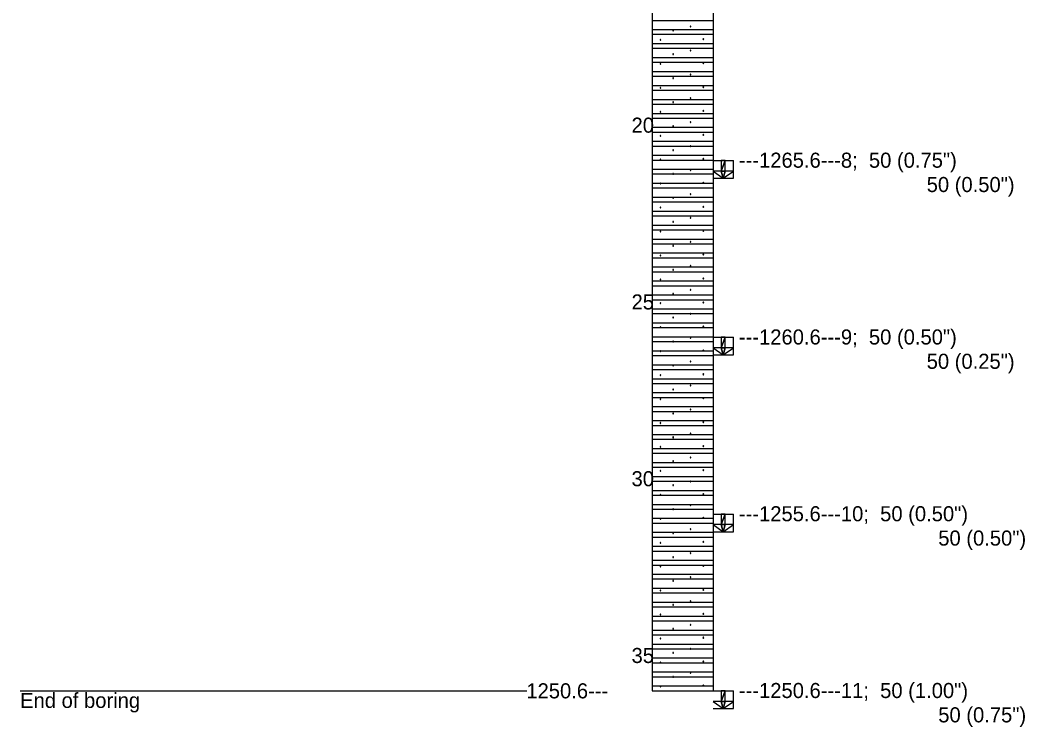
# Model space of a CAD drawing. Extents: x -6 to 173, y 24 to 64.
# Drawn here: x 152.93 to 161.19, y 38.73 to 44.54 of the extents above; entities that cross this region are included whole.
import ezdxf

# ---------------------------------------------------------------- set-up
doc = ezdxf.new("R2010")
doc.units = 0

msp = doc.modelspace()

# ---------------------------------------------------------------- linework, layer by layer
for points in [[(158.1273, 49.4948), (158.1273, 39.0297)], [(158.6273, 49.4948), (158.6273, 39.0297)], [(158.1273, 44.5426), (158.6273, 44.5426)], [(158.1273, 44.4671), (158.6273, 44.4671)], [(158.3024, 44.4605), (158.3008, 44.4634), (158.2975, 44.4634), (158.2958, 44.4606), (158.2975, 44.4577), (158.3008, 44.4577), (158.3024, 44.4605)], [(158.445, 44.4924), (158.4434, 44.4952), (158.4401, 44.4952), (158.4384, 44.4924), (158.4401, 44.4896), (158.4434, 44.4896), (158.445, 44.4924)], [(158.1273, 44.4277), (158.6273, 44.4277)], [(158.1977, 44.3816), (158.1961, 44.3844), (158.1928, 44.3844), (158.1912, 44.3816), (158.1928, 44.3787), (158.1961, 44.3787), (158.1977, 44.3816)], [(158.5505, 44.388), (158.5489, 44.3909), (158.5456, 44.3909), (158.5439, 44.388), (158.5456, 44.3852), (158.5489, 44.3852), (158.5505, 44.388)], [(158.1273, 44.3523), (158.6273, 44.3523)], [(158.1273, 44.3129), (158.6273, 44.3129)], [(158.445, 44.2955), (158.4434, 44.2984), (158.4401, 44.2984), (158.4384, 44.2955), (158.4401, 44.2927), (158.4434, 44.2927), (158.445, 44.2955)], [(158.1273, 44.2375), (158.6273, 44.2375)], [(158.1273, 44.1981), (158.6273, 44.1981)], [(158.3024, 44.2636), (158.3008, 44.2665), (158.2975, 44.2665), (158.2958, 44.2637), (158.2975, 44.2608), (158.3008, 44.2608), (158.3024, 44.2636)], [(158.5505, 44.1912), (158.5489, 44.1941), (158.5456, 44.1941), (158.5439, 44.1912), (158.5456, 44.1884), (158.5489, 44.1884), (158.5505, 44.1912)], [(158.1273, 44.1226), (158.6273, 44.1226)], [(158.1977, 44.1847), (158.1961, 44.1875), (158.1928, 44.1875), (158.1912, 44.1847), (158.1928, 44.1818), (158.1961, 44.1818), (158.1977, 44.1847)], [(158.1273, 44.0833), (158.6273, 44.0833)], [(158.3024, 44.0668), (158.3008, 44.0697), (158.2975, 44.0697), (158.2958, 44.0669), (158.2975, 44.064), (158.3008, 44.064), (158.3024, 44.0668)], [(158.445, 44.0987), (158.4434, 44.1015), (158.4401, 44.1015), (158.4384, 44.0987), (158.4401, 44.0959), (158.4434, 44.0959), (158.445, 44.0987)], [(158.1273, 44.0078), (158.6273, 44.0078)], [(158.1273, 43.9684), (158.6273, 43.9684)], [(158.1977, 43.9879), (158.1961, 43.9907), (158.1928, 43.9907), (158.1912, 43.9879), (158.1928, 43.985), (158.1961, 43.985), (158.1977, 43.9879)], [(158.5505, 43.9943), (158.5489, 43.9972), (158.5456, 43.9972), (158.5439, 43.9943), (158.5456, 43.9915), (158.5489, 43.9915), (158.5505, 43.9943)], [(158.1273, 43.893), (158.6273, 43.893)], [(158.3024, 43.8699), (158.3008, 43.8728), (158.2975, 43.8728), (158.2958, 43.87), (158.2975, 43.8671), (158.3008, 43.8671), (158.3024, 43.8699)], [(158.445, 43.9018), (158.4434, 43.9047), (158.4401, 43.9047), (158.4384, 43.9018), (158.4401, 43.899), (158.4434, 43.899), (158.445, 43.9018)], [(158.1273, 43.8536), (158.6273, 43.8536)], [(158.1977, 43.791), (158.1961, 43.7938), (158.1928, 43.7938), (158.1912, 43.791), (158.1928, 43.7881), (158.1961, 43.7881), (158.1977, 43.791)], [(158.5505, 43.7975), (158.5489, 43.8004), (158.5456, 43.8004), (158.5439, 43.7975), (158.5456, 43.7947), (158.5489, 43.7947), (158.5505, 43.7975)], [(158.1273, 43.7781), (158.6273, 43.7781)], [(158.1273, 43.7388), (158.6273, 43.7388)], [(158.445, 43.705), (158.4434, 43.7078), (158.4401, 43.7078), (158.4384, 43.705), (158.4401, 43.7022), (158.4434, 43.7022), (158.445, 43.705)], [(158.1273, 43.6633), (158.6273, 43.6633)], [(158.1273, 43.6239), (158.6273, 43.6239)], [(158.3024, 43.6731), (158.3008, 43.676), (158.2975, 43.676), (158.2958, 43.6732), (158.2975, 43.6703), (158.3008, 43.6703), (158.3024, 43.6731)], [(158.1273, 43.5485), (158.6273, 43.5485)], [(158.1977, 43.5942), (158.1961, 43.597), (158.1928, 43.597), (158.1912, 43.5942), (158.1928, 43.5913), (158.1961, 43.5913), (158.1977, 43.5942)], [(158.5505, 43.6006), (158.5489, 43.6035), (158.5456, 43.6035), (158.5439, 43.6006), (158.5456, 43.5978), (158.5489, 43.5978), (158.5505, 43.6006)], [(158.1273, 43.5091), (158.6273, 43.5091)], [(158.3024, 43.4762), (158.3008, 43.4791), (158.2975, 43.4791), (158.2958, 43.4763), (158.2975, 43.4734), (158.3008, 43.4734), (158.3024, 43.4762)], [(158.445, 43.5081), (158.4434, 43.5109), (158.4401, 43.5109), (158.4384, 43.5081), (158.4401, 43.5053), (158.4434, 43.5053), (158.445, 43.5081)], [(158.1273, 43.4337), (158.6273, 43.4337)], [(158.1273, 43.3943), (158.6273, 43.3943)], [(158.1977, 43.3973), (158.1961, 43.4001), (158.1928, 43.4001), (158.1912, 43.3973), (158.1928, 43.3944), (158.1961, 43.3944), (158.1977, 43.3973)], [(158.5505, 43.4038), (158.5489, 43.4067), (158.5456, 43.4067), (158.5439, 43.4038), (158.5456, 43.401), (158.5489, 43.401), (158.5505, 43.4038)], [(158.6273, 43.3902), (158.794, 43.3902)], [(158.794, 43.2448), (158.794, 43.3902)], [(158.1273, 43.3188), (158.6273, 43.3188)], [(158.445, 43.3113), (158.4434, 43.3141), (158.4401, 43.3141), (158.4384, 43.3113), (158.4401, 43.3085), (158.4434, 43.3085), (158.445, 43.3113)], [(158.1273, 43.2795), (158.6273, 43.2795)], [(158.1273, 43.204), (158.6273, 43.204)], [(158.1977, 43.2005), (158.1961, 43.2033), (158.1928, 43.2033), (158.1912, 43.2005), (158.1928, 43.1976), (158.1961, 43.1976), (158.1977, 43.2005)], [(158.3024, 43.2794), (158.3008, 43.2823), (158.2975, 43.2823), (158.2958, 43.2795), (158.2975, 43.2766), (158.3008, 43.2766), (158.3024, 43.2794)], [(158.5505, 43.2069), (158.5489, 43.2098), (158.5456, 43.2098), (158.5439, 43.2069), (158.5456, 43.2041), (158.5489, 43.2041), (158.5505, 43.2069)], [(158.6273, 43.2448), (158.794, 43.2448)], [(158.1273, 43.1646), (158.6273, 43.1646)], [(158.1273, 43.0892), (158.6273, 43.0892)], [(158.1273, 43.0498), (158.6273, 43.0498)], [(158.3024, 43.0825), (158.3008, 43.0854), (158.2975, 43.0854), (158.2958, 43.0826), (158.2975, 43.0797), (158.3008, 43.0797), (158.3024, 43.0825)], [(158.445, 43.1144), (158.4434, 43.1172), (158.4401, 43.1172), (158.4384, 43.1144), (158.4401, 43.1116), (158.4434, 43.1116), (158.445, 43.1144)], [(158.1273, 42.9743), (158.6273, 42.9743)], [(158.1977, 43.0036), (158.1961, 43.0064), (158.1928, 43.0064), (158.1912, 43.0036), (158.1928, 43.0007), (158.1961, 43.0007), (158.1977, 43.0036)], [(158.5505, 43.0101), (158.5489, 43.013), (158.5456, 43.013), (158.5439, 43.0101), (158.5456, 43.0073), (158.5489, 43.0073), (158.5505, 43.0101)], [(158.1273, 42.935), (158.6273, 42.935)], [(158.3024, 42.8857), (158.3008, 42.8886), (158.2975, 42.8886), (158.2958, 42.8858), (158.2975, 42.8829), (158.3008, 42.8829), (158.3024, 42.8857)], [(158.445, 42.9176), (158.4434, 42.9204), (158.4401, 42.9204), (158.4384, 42.9176), (158.4401, 42.9148), (158.4434, 42.9148), (158.445, 42.9176)], [(158.1273, 42.8595), (158.6273, 42.8595)], [(158.1273, 42.8201), (158.6273, 42.8201)], [(158.1977, 42.8068), (158.1961, 42.8096), (158.1928, 42.8096), (158.1912, 42.8068), (158.1928, 42.8039), (158.1961, 42.8039), (158.1977, 42.8068)], [(158.5505, 42.8132), (158.5489, 42.8161), (158.5456, 42.8161), (158.5439, 42.8132), (158.5456, 42.8104), (158.5489, 42.8104), (158.5505, 42.8132)], [(158.1273, 42.7447), (158.6273, 42.7447)], [(158.1273, 42.7053), (158.6273, 42.7053)], [(158.445, 42.7207), (158.4434, 42.7235), (158.4401, 42.7235), (158.4384, 42.7207), (158.4401, 42.7179), (158.4434, 42.7179), (158.445, 42.7207)], [(158.1273, 42.6298), (158.6273, 42.6298)], [(158.3024, 42.6888), (158.3008, 42.6917), (158.2975, 42.6917), (158.2958, 42.6889), (158.2975, 42.686), (158.3008, 42.686), (158.3024, 42.6888)], [(158.1273, 42.5905), (158.6273, 42.5905)], [(158.1977, 42.6099), (158.1961, 42.6127), (158.1928, 42.6127), (158.1912, 42.6099), (158.1928, 42.607), (158.1961, 42.607), (158.1977, 42.6099)], [(158.5505, 42.6164), (158.5489, 42.6193), (158.5456, 42.6193), (158.5439, 42.6164), (158.5456, 42.6136), (158.5489, 42.6136), (158.5505, 42.6164)], [(158.1273, 42.515), (158.6273, 42.515)], [(158.1273, 42.4756), (158.6273, 42.4756)], [(158.3024, 42.492), (158.3008, 42.4949), (158.2975, 42.4949), (158.2958, 42.4921), (158.2975, 42.4892), (158.3008, 42.4892), (158.3024, 42.492)], [(158.445, 42.5239), (158.4434, 42.5267), (158.4401, 42.5267), (158.4384, 42.5239), (158.4401, 42.5211), (158.4434, 42.5211), (158.445, 42.5239)], [(158.1273, 42.4002), (158.6273, 42.4002)], [(158.1977, 42.413), (158.1961, 42.4159), (158.1928, 42.4159), (158.1912, 42.413), (158.1928, 42.4102), (158.1961, 42.4102), (158.1977, 42.413)], [(158.5505, 42.4195), (158.5489, 42.4224), (158.5456, 42.4224), (158.5439, 42.4195), (158.5456, 42.4167), (158.5489, 42.4167), (158.5505, 42.4195)], [(158.1273, 42.3608), (158.6273, 42.3608)], [(158.3024, 42.2951), (158.3008, 42.298), (158.2975, 42.298), (158.2958, 42.2952), (158.2975, 42.2923), (158.3008, 42.2923), (158.3024, 42.2951)], [(158.445, 42.327), (158.4434, 42.3298), (158.4401, 42.3298), (158.4384, 42.327), (158.4401, 42.3242), (158.4434, 42.3242), (158.445, 42.327)], [(158.1273, 42.2854), (158.6273, 42.2854)], [(158.1273, 42.246), (158.6273, 42.246)], [(158.1977, 42.2162), (158.1961, 42.219), (158.1928, 42.219), (158.1912, 42.2162), (158.1928, 42.2133), (158.1961, 42.2133), (158.1977, 42.2162)], [(158.5505, 42.2227), (158.5489, 42.2256), (158.5456, 42.2256), (158.5439, 42.2227), (158.5456, 42.2199), (158.5489, 42.2199), (158.5505, 42.2227)], [(158.1273, 42.1705), (158.6273, 42.1705)], [(158.1273, 42.1312), (158.6273, 42.1312)], [(158.445, 42.1302), (158.4434, 42.133), (158.4401, 42.133), (158.4384, 42.1302), (158.4401, 42.1274), (158.4434, 42.1274), (158.445, 42.1302)], [(158.1273, 42.0557), (158.6273, 42.0557)], [(158.3024, 42.0983), (158.3008, 42.1012), (158.2975, 42.1012), (158.2958, 42.0984), (158.2975, 42.0955), (158.3008, 42.0955), (158.3024, 42.0983)], [(158.1273, 42.0163), (158.6273, 42.0163)], [(158.1977, 42.0193), (158.1961, 42.0222), (158.1928, 42.0222), (158.1912, 42.0193), (158.1928, 42.0165), (158.1961, 42.0165), (158.1977, 42.0193)], [(158.5505, 42.0258), (158.5489, 42.0287), (158.5456, 42.0287), (158.5439, 42.0258), (158.5456, 42.023), (158.5489, 42.023), (158.5505, 42.0258)], [(158.1273, 41.9409), (158.6273, 41.9409)], [(158.1273, 41.9015), (158.6273, 41.9015)], [(158.3024, 41.9014), (158.3008, 41.9043), (158.2975, 41.9043), (158.2958, 41.9015), (158.2975, 41.8986), (158.3008, 41.8986), (158.3024, 41.9014)], [(158.445, 41.9333), (158.4434, 41.9361), (158.4401, 41.9361), (158.4384, 41.9333), (158.4401, 41.9305), (158.4434, 41.9305), (158.445, 41.9333)], [(158.6273, 41.9367), (158.794, 41.9367)], [(158.794, 41.7913), (158.794, 41.9367)], [(158.1273, 41.826), (158.6273, 41.826)], [(158.1977, 41.8225), (158.1961, 41.8253), (158.1928, 41.8253), (158.1912, 41.8225), (158.1928, 41.8196), (158.1961, 41.8196), (158.1977, 41.8225)], [(158.5505, 41.829), (158.5489, 41.8319), (158.5456, 41.8319), (158.5439, 41.829), (158.5456, 41.8262), (158.5489, 41.8262), (158.5505, 41.829)], [(158.1273, 41.7867), (158.6273, 41.7867)], [(158.445, 41.7365), (158.4434, 41.7393), (158.4401, 41.7393), (158.4384, 41.7365), (158.4401, 41.7337), (158.4434, 41.7337), (158.445, 41.7365)], [(158.6273, 41.7913), (158.794, 41.7913)], [(158.1273, 41.7112), (158.6273, 41.7112)], [(158.1273, 41.6718), (158.6273, 41.6718)], [(158.3024, 41.7046), (158.3008, 41.7075), (158.2975, 41.7075), (158.2958, 41.7047), (158.2975, 41.7018), (158.3008, 41.7018), (158.3024, 41.7046)], [(158.5505, 41.6321), (158.5489, 41.635), (158.5456, 41.635), (158.5439, 41.6321), (158.5456, 41.6293), (158.5489, 41.6293), (158.5505, 41.6321)], [(158.1273, 41.5964), (158.6273, 41.5964)], [(158.1273, 41.557), (158.6273, 41.557)], [(158.1977, 41.6256), (158.1961, 41.6285), (158.1928, 41.6285), (158.1912, 41.6256), (158.1928, 41.6228), (158.1961, 41.6228), (158.1977, 41.6256)], [(158.1273, 41.4816), (158.6273, 41.4816)], [(158.3024, 41.5077), (158.3008, 41.5106), (158.2975, 41.5106), (158.2958, 41.5078), (158.2975, 41.5049), (158.3008, 41.5049), (158.3024, 41.5077)], [(158.445, 41.5396), (158.4434, 41.5424), (158.4401, 41.5424), (158.4384, 41.5396), (158.4401, 41.5368), (158.4434, 41.5368), (158.445, 41.5396)], [(158.1273, 41.4422), (158.6273, 41.4422)], [(158.1977, 41.4288), (158.1961, 41.4316), (158.1928, 41.4316), (158.1912, 41.4288), (158.1928, 41.4259), (158.1961, 41.4259), (158.1977, 41.4288)], [(158.5505, 41.4353), (158.5489, 41.4382), (158.5456, 41.4382), (158.5439, 41.4353), (158.5456, 41.4325), (158.5489, 41.4325), (158.5505, 41.4353)], [(158.1273, 41.3667), (158.6273, 41.3667)], [(158.1273, 41.3274), (158.6273, 41.3274)], [(158.3024, 41.3109), (158.3008, 41.3138), (158.2975, 41.3138), (158.2958, 41.3109), (158.2975, 41.3081), (158.3008, 41.3081), (158.3024, 41.3109)], [(158.445, 41.3428), (158.4434, 41.3456), (158.4401, 41.3456), (158.4384, 41.3428), (158.4401, 41.34), (158.4434, 41.34), (158.445, 41.3428)], [(158.1273, 41.2519), (158.6273, 41.2519)], [(158.1977, 41.2319), (158.1961, 41.2348), (158.1928, 41.2348), (158.1912, 41.2319), (158.1928, 41.2291), (158.1961, 41.2291), (158.1977, 41.2319)], [(158.5505, 41.2384), (158.5489, 41.2413), (158.5456, 41.2413), (158.5439, 41.2384), (158.5456, 41.2356), (158.5489, 41.2356), (158.5505, 41.2384)], [(158.1273, 41.2125), (158.6273, 41.2125)], [(158.1273, 41.1371), (158.6273, 41.1371)], [(158.445, 41.1459), (158.4434, 41.1487), (158.4401, 41.1487), (158.4384, 41.1459), (158.4401, 41.1431), (158.4434, 41.1431), (158.445, 41.1459)], [(158.1273, 41.0977), (158.6273, 41.0977)], [(158.3024, 41.114), (158.3008, 41.1169), (158.2975, 41.1169), (158.2958, 41.1141), (158.2975, 41.1112), (158.3008, 41.1112), (158.3024, 41.114)], [(158.1273, 41.0222), (158.6273, 41.0222)], [(158.1273, 40.9829), (158.6273, 40.9829)], [(158.1977, 41.0351), (158.1961, 41.0379), (158.1928, 41.0379), (158.1912, 41.0351), (158.1928, 41.0322), (158.1961, 41.0322), (158.1977, 41.0351)], [(158.5505, 41.0416), (158.5489, 41.0445), (158.5456, 41.0445), (158.5439, 41.0416), (158.5456, 41.0388), (158.5489, 41.0388), (158.5505, 41.0416)], [(158.1273, 40.9074), (158.6273, 40.9074)], [(158.3024, 40.9172), (158.3008, 40.9201), (158.2975, 40.9201), (158.2958, 40.9172), (158.2975, 40.9144), (158.3008, 40.9144), (158.3024, 40.9172)], [(158.445, 40.9491), (158.4434, 40.9519), (158.4401, 40.9519), (158.4384, 40.9491), (158.4401, 40.9463), (158.4434, 40.9463), (158.445, 40.9491)], [(158.1273, 40.868), (158.6273, 40.868)], [(158.1977, 40.8382), (158.1961, 40.8411), (158.1928, 40.8411), (158.1912, 40.8382), (158.1928, 40.8354), (158.1961, 40.8354), (158.1977, 40.8382)], [(158.5505, 40.8447), (158.5489, 40.8476), (158.5456, 40.8476), (158.5439, 40.8447), (158.5456, 40.8419), (158.5489, 40.8419), (158.5505, 40.8447)], [(158.1273, 40.7926), (158.6273, 40.7926)], [(158.1273, 40.7532), (158.6273, 40.7532)], [(158.3024, 40.7203), (158.3008, 40.7232), (158.2975, 40.7232), (158.2958, 40.7204), (158.2975, 40.7175), (158.3008, 40.7175), (158.3024, 40.7203)], [(158.445, 40.7522), (158.4434, 40.755), (158.4401, 40.755), (158.4384, 40.7522), (158.4401, 40.7494), (158.4434, 40.7494), (158.445, 40.7522)], [(158.1273, 40.6777), (158.6273, 40.6777)], [(158.1977, 40.6414), (158.1961, 40.6442), (158.1928, 40.6442), (158.1912, 40.6414), (158.1928, 40.6385), (158.1961, 40.6385), (158.1977, 40.6414)], [(158.5505, 40.6479), (158.5489, 40.6508), (158.5456, 40.6508), (158.5439, 40.6479), (158.5456, 40.6451), (158.5489, 40.6451), (158.5505, 40.6479)], [(158.1273, 40.6384), (158.6273, 40.6384)], [(158.1273, 40.5629), (158.6273, 40.5629)], [(158.445, 40.5554), (158.4434, 40.5582), (158.4401, 40.5582), (158.4384, 40.5554), (158.4401, 40.5526), (158.4434, 40.5526), (158.445, 40.5554)], [(158.1273, 40.5235), (158.6273, 40.5235)], [(158.3024, 40.5235), (158.3008, 40.5264), (158.2975, 40.5264), (158.2958, 40.5235), (158.2975, 40.5207), (158.3008, 40.5207), (158.3024, 40.5235)], [(158.6273, 40.4832), (158.794, 40.4832)], [(158.794, 40.3378), (158.794, 40.4832)], [(158.1273, 40.4481), (158.6273, 40.4481)], [(158.1273, 40.4087), (158.6273, 40.4087)], [(158.1977, 40.4445), (158.1961, 40.4474), (158.1928, 40.4474), (158.1912, 40.4445), (158.1928, 40.4417), (158.1961, 40.4417), (158.1977, 40.4445)], [(158.5505, 40.451), (158.5489, 40.4539), (158.5456, 40.4539), (158.5439, 40.451), (158.5456, 40.4482), (158.5489, 40.4482), (158.5505, 40.451)], [(158.1273, 40.3333), (158.6273, 40.3333)], [(158.3024, 40.3266), (158.3008, 40.3295), (158.2975, 40.3295), (158.2958, 40.3267), (158.2975, 40.3238), (158.3008, 40.3238), (158.3024, 40.3266)], [(158.445, 40.3585), (158.4434, 40.3613), (158.4401, 40.3613), (158.4384, 40.3585), (158.4401, 40.3557), (158.4434, 40.3557), (158.445, 40.3585)], [(158.6273, 40.3378), (158.794, 40.3378)], [(158.1273, 40.2939), (158.6273, 40.2939)], [(158.1977, 40.2477), (158.1961, 40.2505), (158.1928, 40.2505), (158.1912, 40.2477), (158.1928, 40.2448), (158.1961, 40.2448), (158.1977, 40.2477)], [(158.5505, 40.2542), (158.5489, 40.2571), (158.5456, 40.2571), (158.5439, 40.2542), (158.5456, 40.2514), (158.5489, 40.2514), (158.5505, 40.2542)], [(158.1273, 40.2184), (158.6273, 40.2184)], [(158.1273, 40.1791), (158.6273, 40.1791)], [(158.445, 40.1617), (158.4434, 40.1645), (158.4401, 40.1645), (158.4384, 40.1617), (158.4401, 40.1588), (158.4434, 40.1588), (158.445, 40.1617)], [(158.1273, 40.1036), (158.6273, 40.1036)], [(158.1273, 40.0642), (158.6273, 40.0642)], [(158.3024, 40.1298), (158.3008, 40.1327), (158.2975, 40.1327), (158.2958, 40.1298), (158.2975, 40.127), (158.3008, 40.127), (158.3024, 40.1298)], [(158.1273, 39.9888), (158.6273, 39.9888)], [(158.1977, 40.0508), (158.1961, 40.0537), (158.1928, 40.0537), (158.1912, 40.0508), (158.1928, 40.048), (158.1961, 40.048), (158.1977, 40.0508)], [(158.5505, 40.0573), (158.5489, 40.0602), (158.5456, 40.0602), (158.5439, 40.0573), (158.5456, 40.0545), (158.5489, 40.0545), (158.5505, 40.0573)], [(158.1273, 39.9494), (158.6273, 39.9494)], [(158.3024, 39.9329), (158.3008, 39.9358), (158.2975, 39.9358), (158.2958, 39.933), (158.2975, 39.9301), (158.3008, 39.9301), (158.3024, 39.9329)], [(158.445, 39.9648), (158.4434, 39.9676), (158.4401, 39.9676), (158.4384, 39.9648), (158.4401, 39.962), (158.4434, 39.962), (158.445, 39.9648)], [(158.1273, 39.8739), (158.6273, 39.8739)], [(158.1273, 39.8346), (158.6273, 39.8346)], [(158.1977, 39.854), (158.1961, 39.8568), (158.1928, 39.8568), (158.1912, 39.854), (158.1928, 39.8511), (158.1961, 39.8511), (158.1977, 39.854)], [(158.5505, 39.8605), (158.5489, 39.8634), (158.5456, 39.8634), (158.5439, 39.8605), (158.5456, 39.8577), (158.5489, 39.8577), (158.5505, 39.8605)], [(158.1273, 39.7591), (158.6273, 39.7591)], [(158.3024, 39.7361), (158.3008, 39.739), (158.2975, 39.739), (158.2958, 39.7361), (158.2975, 39.7333), (158.3008, 39.7333), (158.3024, 39.7361)], [(158.445, 39.768), (158.4434, 39.7708), (158.4401, 39.7708), (158.4384, 39.768), (158.4401, 39.7651), (158.4434, 39.7651), (158.445, 39.768)], [(158.1273, 39.7197), (158.6273, 39.7197)], [(158.1977, 39.6571), (158.1961, 39.66), (158.1928, 39.66), (158.1912, 39.6571), (158.1928, 39.6543), (158.1961, 39.6543), (158.1977, 39.6571)], [(158.5505, 39.6636), (158.5489, 39.6665), (158.5456, 39.6665), (158.5439, 39.6636), (158.5456, 39.6608), (158.5489, 39.6608), (158.5505, 39.6636)], [(158.1273, 39.6443), (158.6273, 39.6443)], [(158.1273, 39.6049), (158.6273, 39.6049)], [(158.445, 39.5711), (158.4434, 39.5739), (158.4401, 39.5739), (158.4384, 39.5711), (158.4401, 39.5683), (158.4434, 39.5683), (158.445, 39.5711)], [(158.1273, 39.5295), (158.6273, 39.5295)], [(158.1273, 39.4901), (158.6273, 39.4901)], [(158.3024, 39.5392), (158.3008, 39.5421), (158.2975, 39.5421), (158.2958, 39.5393), (158.2975, 39.5364), (158.3008, 39.5364), (158.3024, 39.5392)], [(158.1273, 39.4146), (158.6273, 39.4146)], [(158.1977, 39.4603), (158.1961, 39.4631), (158.1928, 39.4631), (158.1912, 39.4603), (158.1928, 39.4574), (158.1961, 39.4574), (158.1977, 39.4603)], [(158.5505, 39.4668), (158.5489, 39.4697), (158.5456, 39.4697), (158.5439, 39.4668), (158.5456, 39.464), (158.5489, 39.464), (158.5505, 39.4668)], [(158.1273, 39.3753), (158.6273, 39.3753)], [(158.3024, 39.3424), (158.3008, 39.3453), (158.2975, 39.3453), (158.2958, 39.3424), (158.2975, 39.3396), (158.3008, 39.3396), (158.3024, 39.3424)], [(158.445, 39.3743), (158.4434, 39.3771), (158.4401, 39.3771), (158.4384, 39.3743), (158.4401, 39.3714), (158.4434, 39.3714), (158.445, 39.3743)], [(158.1273, 39.2998), (158.6273, 39.2998)], [(158.1273, 39.2604), (158.6273, 39.2604)], [(158.1977, 39.2634), (158.1961, 39.2663), (158.1928, 39.2663), (158.1912, 39.2634), (158.1928, 39.2606), (158.1961, 39.2606), (158.1977, 39.2634)], [(158.5505, 39.2699), (158.5489, 39.2728), (158.5456, 39.2728), (158.5439, 39.2699), (158.5456, 39.2671), (158.5489, 39.2671), (158.5505, 39.2699)], [(158.1273, 39.185), (158.6273, 39.185)], [(158.445, 39.1774), (158.4434, 39.1802), (158.4401, 39.1802), (158.4384, 39.1774), (158.4401, 39.1746), (158.4434, 39.1746), (158.445, 39.1774)], [(158.1273, 39.1456), (158.6273, 39.1456)], [(158.1273, 39.0701), (158.6273, 39.0701)], [(158.3024, 39.1455), (158.3008, 39.1484), (158.2975, 39.1484), (158.2958, 39.1456), (158.2975, 39.1427), (158.3008, 39.1427), (158.3024, 39.1455)], [(158.5505, 39.0731), (158.5489, 39.076), (158.5456, 39.076), (158.5439, 39.0731), (158.5456, 39.0703), (158.5489, 39.0703), (158.5505, 39.0731)], [(152.9304, 39.0297), (157.097, 39.0297)], [(158.1273, 39.0308), (158.6273, 39.0308)], [(158.1273, 39.0297), (158.6273, 39.0297)], [(158.1977, 39.0666), (158.1961, 39.0694), (158.1928, 39.0694), (158.1912, 39.0666), (158.1928, 39.0637), (158.1961, 39.0637), (158.1977, 39.0666)], [(158.6273, 39.0297), (158.794, 39.0297)], [(158.794, 38.8843), (158.794, 39.0297)], [(158.6273, 38.8843), (158.794, 38.8843)]]:
    msp.add_lwpolyline(points)
for points in [[(158.694, 43.303), (158.7273, 43.303), (158.7273, 43.3902), (158.694, 43.303)], [(158.694, 43.303), (158.7273, 43.3902), (158.694, 43.3902), (158.694, 43.303)], [(158.694, 43.303), (158.6273, 43.303), (158.7107, 43.2448), (158.694, 43.303)], [(158.694, 43.303), (158.7107, 43.2448), (158.7273, 43.303), (158.694, 43.303)], [(158.7107, 43.2448), (158.794, 43.303), (158.7273, 43.303), (158.7107, 43.2448)], [(158.694, 41.8495), (158.7273, 41.8495), (158.7273, 41.9367), (158.694, 41.8495)], [(158.694, 41.8495), (158.7273, 41.9367), (158.694, 41.9367), (158.694, 41.8495)], [(158.694, 41.8495), (158.6273, 41.8495), (158.7107, 41.7913), (158.694, 41.8495)], [(158.694, 41.8495), (158.7107, 41.7913), (158.7273, 41.8495), (158.694, 41.8495)], [(158.7107, 41.7913), (158.794, 41.8495), (158.7273, 41.8495), (158.7107, 41.7913)], [(158.694, 40.396), (158.7273, 40.396), (158.7273, 40.4832), (158.694, 40.396)], [(158.694, 40.396), (158.7273, 40.4832), (158.694, 40.4832), (158.694, 40.396)], [(158.694, 40.396), (158.6273, 40.396), (158.7107, 40.3378), (158.694, 40.396)], [(158.694, 40.396), (158.7107, 40.3378), (158.7273, 40.396), (158.694, 40.396)], [(158.7107, 40.3378), (158.794, 40.396), (158.7273, 40.396), (158.7107, 40.3378)], [(158.694, 38.9425), (158.7273, 38.9425), (158.7273, 39.0297), (158.694, 38.9425)], [(158.694, 38.9425), (158.7273, 39.0297), (158.694, 39.0297), (158.694, 38.9425)], [(158.694, 38.9425), (158.6273, 38.9425), (158.7107, 38.8843), (158.694, 38.9425)], [(158.694, 38.9425), (158.7107, 38.8843), (158.7273, 38.9425), (158.694, 38.9425)], [(158.7107, 38.8843), (158.794, 38.9425), (158.7273, 38.9425), (158.7107, 38.8843)]]:
    msp.add_lwpolyline(points, close=True)

# ---------------------------------------------------------------- texts
for s, p in [('20', (157.9569, 43.6189)), ('---1265.6---8;  50 (0.75")', (158.8393, 43.3308)), ('50 (0.50")', (160.383, 43.1308)), ('25', (157.9569, 42.1654)), ('---1260.6---9;  50 (0.50")', (158.8393, 41.8773)), ('50 (0.25")', (160.383, 41.6773)), ('30', (157.9569, 40.7119)), ('---1255.6---10;  50 (0.50")', (158.8393, 40.4239)), ('50 (0.50")', (160.4782, 40.2239)), ('35', (157.9569, 39.2584)), ('1250.6---', (157.0921, 38.9677)), ('---1250.6---11;  50 (1.00")', (158.8393, 38.9704)), ('End of boring', (152.9304, 38.889)), ('50 (0.75")', (160.4782, 38.7704))]:
    msp.add_text(s, height=0.124).set_placement(p)

doc.saveas('drawing.dxf')
